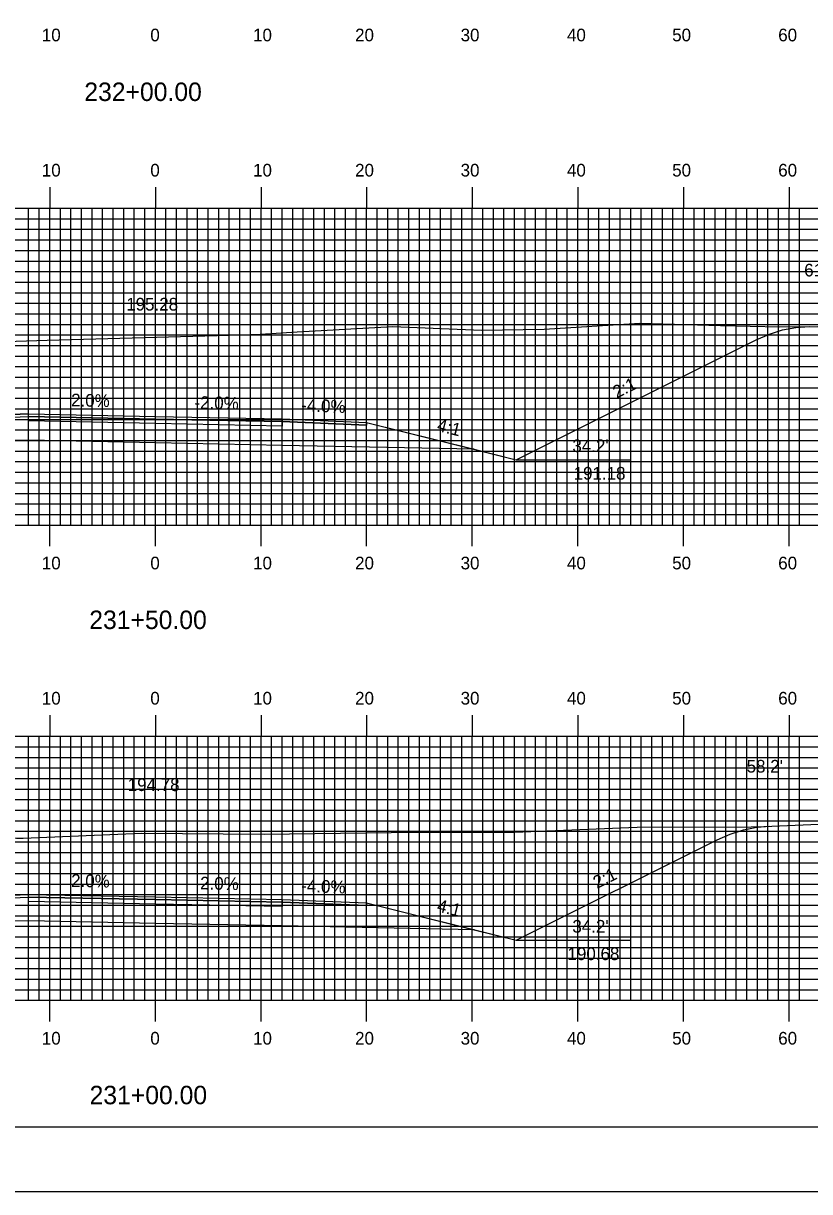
# Model space of a CAD drawing. Extents: x 1799568 to 1799912, y 442591 to 442811.
# Drawn here: x 1799721.5 to 1799796, y 442590.5 to 442701.2 of the extents above; entities that cross this region are included whole.
import ezdxf

# ---------------------------------------------------------------- set-up
doc = ezdxf.new("R2010")
doc.units = 0
for name, color, linetype in [('ANNOTATION', 7, 'Continuous'), ('BORDER', 7, 'Continuous'), ('D_Roadway_Centerline', 7, 'Continuous'), ('D_Roadway_Centerline_Text', 7, 'Continuous'), ('D_Roadway_Edge_Shoulder', 7, 'Continuous'), ('D_Roadway_Edge_TW', 7, 'Continuous'), ('D_Roadway_Pavement', 7, 'Continuous'), ('D_Roadway_SlopeLines', 7, 'Continuous'), ('D_Roadway_SubGrade', 7, 'Continuous'), ('D_Text_Standard', 7, 'Continuous'), ('H_V ANNOTATION', 7, 'Continuous'), ('MAJOR', 7, 'Continuous'), ('MINOR', 7, 'Continuous'), ('PDRAIN', 7, 'Continuous'), ('PLOT BOUNDARY', 7, 'Continuous'), ('S_Roadway_Centerline', 7, 'Continuous')]:
    doc.layers.add(name, color=color, linetype=linetype)

msp = doc.modelspace()

# ---------------------------------------------------------------- linework, layer by layer
at = {"layer": 'BORDER'}
msp.add_lwpolyline([(1799584.41, 442596.67), (1799904.41, 442596.67), (1799904.41, 442806.67), (1799584.41, 442806.67)], close=True, dxfattribs=at)
at = {"layer": 'D_Roadway_Centerline'}
for points in [[(1799677.91, 442669.95), (1799679.16, 442669.91), (1799680.41, 442669.7), (1799681.66, 442669.33), (1799682.91, 442668.79), (1799699.84, 442660.33), (1799703.84, 442661.33), (1799714.01, 442663.87), (1799722.01, 442664.19), (1799734.01, 442663.95), (1799746.01, 442663.71), (1799754.01, 442663.39), (1799764.18, 442660.85), (1799768.18, 442659.85), (1799790.9, 442671.2), (1799792.15, 442671.75), (1799793.4, 442672.14), (1799794.65, 442672.38), (1799795.9, 442672.47)], [(1799679.47, 442623.7), (1799680.72, 442623.65), (1799681.97, 442623.43), (1799683.22, 442623.05), (1799684.47, 442622.51), (1799699.84, 442614.83), (1799703.84, 442615.83), (1799714.01, 442618.37), (1799722.01, 442618.69), (1799734.01, 442618.45), (1799746.01, 442618.21), (1799754.01, 442617.89), (1799764.18, 442615.35), (1799768.18, 442614.35), (1799787.19, 442623.85), (1799788.44, 442624.4), (1799789.69, 442624.8), (1799790.94, 442625.05), (1799792.19, 442625.15)]]:
    msp.add_lwpolyline(points, dxfattribs=at)
at = {"layer": 'D_Roadway_Edge_Shoulder'}
for points in [[(1799722.01, 442664.19), (1799714.01, 442663.87), (1799714.01, 442663.62), (1799722.01, 442663.94)], [(1799746.01, 442663.71), (1799754.01, 442663.39), (1799754.01, 442663.14), (1799746.01, 442663.46)], [(1799722.01, 442618.69), (1799714.01, 442618.37), (1799714.01, 442618.12), (1799722.01, 442618.44)], [(1799746.01, 442618.21), (1799754.01, 442617.89), (1799754.01, 442617.64), (1799746.01, 442617.96)]]:
    msp.add_lwpolyline(points, close=True, dxfattribs=at)
at = {"layer": 'D_Roadway_Edge_TW'}
for points in [[(1799722.01, 442663.94), (1799722.01, 442664.19), (1799734.01, 442663.95), (1799746.01, 442663.71), (1799746.01, 442663.46), (1799734.01, 442663.7)], [(1799722.01, 442618.44), (1799722.01, 442618.69), (1799734.01, 442618.45), (1799746.01, 442618.21), (1799746.01, 442617.96), (1799734.01, 442618.2)]]:
    msp.add_lwpolyline(points, close=True, dxfattribs=at)
at = {"layer": 'D_Roadway_Pavement'}
for points in [[(1799722.01, 442663.52), (1799722.01, 442663.94), (1799734.01, 442663.7), (1799746.01, 442663.46), (1799746.01, 442663.04), (1799734.01, 442663.28)], [(1799722.01, 442618.02), (1799722.01, 442618.44), (1799734.01, 442618.2), (1799746.01, 442617.96), (1799746.01, 442617.54), (1799734.01, 442617.78)]]:
    msp.add_lwpolyline(points, close=True, dxfattribs=at)
at = {"layer": 'D_Roadway_SlopeLines'}
for points in [[(1799768.18, 442659.85), (1799790.9, 442671.2), (1799792.15, 442671.75), (1799793.4, 442672.14), (1799794.65, 442672.38), (1799795.9, 442672.47)], [(1799754.01, 442663.39), (1799768.18, 442659.85)], [(1799768.18, 442614.35), (1799787.19, 442623.85), (1799788.44, 442624.4), (1799789.69, 442624.8), (1799790.94, 442625.05), (1799792.19, 442625.15)], [(1799754.01, 442617.89), (1799768.18, 442614.35)]]:
    msp.add_lwpolyline(points, dxfattribs=at)
at = {"layer": 'D_Roadway_SubGrade'}
for points in [[(1799722.01, 442661.69), (1799703.84, 442661.33), (1799714.01, 442663.87), (1799714.01, 442663.62), (1799722.01, 442663.94), (1799734.01, 442663.7), (1799746.01, 442663.46), (1799754.01, 442663.14), (1799754.01, 442663.39), (1799764.18, 442660.85), (1799746.01, 442661.21), (1799734.01, 442661.45)], [(1799722.01, 442616.19), (1799703.84, 442615.83), (1799714.01, 442618.37), (1799714.01, 442618.12), (1799722.01, 442618.44), (1799734.01, 442618.2), (1799746.01, 442617.96), (1799754.01, 442617.64), (1799754.01, 442617.89), (1799764.18, 442615.35), (1799746.01, 442615.71), (1799734.01, 442615.95)]]:
    msp.add_lwpolyline(points, close=True, dxfattribs=at)
at = {"layer": 'MAJOR'}
for p, q in [((1799724.01, 442685.67), (1799724.01, 442683.67)), ((1799734.01, 442685.67), (1799734.01, 442683.67)), ((1799744.01, 442685.67), (1799744.01, 442683.67)), ((1799754.01, 442685.67), (1799754.01, 442683.67)), ((1799764.01, 442685.67), (1799764.01, 442683.67)), ((1799774.01, 442685.67), (1799774.01, 442683.67)), ((1799784.01, 442685.67), (1799784.01, 442683.67)), ((1799794.01, 442685.67), (1799794.01, 442683.67)), ((1799594.01, 442683.67), (1799874.01, 442683.67)), ((1799594.01, 442683.67), (1799874.01, 442683.67)), ((1799724.01, 442653.67), (1799724.01, 442683.67)), ((1799734.01, 442653.67), (1799734.01, 442683.67)), ((1799744.01, 442653.67), (1799744.01, 442683.67)), ((1799754.01, 442653.67), (1799754.01, 442683.67)), ((1799764.01, 442653.67), (1799764.01, 442683.67)), ((1799774.01, 442653.67), (1799774.01, 442683.67)), ((1799784.01, 442653.67), (1799784.01, 442683.67)), ((1799794.01, 442653.67), (1799794.01, 442683.67)), ((1799594.01, 442678.67), (1799874.01, 442678.67)), ((1799594.01, 442673.67), (1799874.01, 442673.67)), ((1799594.01, 442668.67), (1799874.01, 442668.67)), ((1799594.01, 442663.67), (1799874.01, 442663.67)), ((1799594.01, 442658.67), (1799874.01, 442658.67)), ((1799594.01, 442653.67), (1799874.01, 442653.67)), ((1799594.01, 442653.67), (1799874.01, 442653.67)), ((1799724.01, 442651.66), (1799724.01, 442653.67)), ((1799734.01, 442651.66), (1799734.01, 442653.67)), ((1799744.01, 442651.66), (1799744.01, 442653.67)), ((1799754.01, 442651.66), (1799754.01, 442653.67)), ((1799764.01, 442651.66), (1799764.01, 442653.67)), ((1799774.01, 442651.66), (1799774.01, 442653.67)), ((1799784.01, 442651.66), (1799784.01, 442653.67)), ((1799794.01, 442651.66), (1799794.01, 442653.67)), ((1799724.01, 442635.67), (1799724.01, 442633.67)), ((1799734.01, 442635.67), (1799734.01, 442633.67)), ((1799744.01, 442635.67), (1799744.01, 442633.67)), ((1799754.01, 442635.67), (1799754.01, 442633.67)), ((1799764.01, 442635.67), (1799764.01, 442633.67)), ((1799774.01, 442635.67), (1799774.01, 442633.67)), ((1799784.01, 442635.67), (1799784.01, 442633.67)), ((1799794.01, 442635.67), (1799794.01, 442633.67)), ((1799594.01, 442633.67), (1799874.01, 442633.67)), ((1799594.01, 442633.67), (1799874.01, 442633.67)), ((1799724.01, 442608.67), (1799724.01, 442633.67)), ((1799734.01, 442608.67), (1799734.01, 442633.67)), ((1799744.01, 442608.67), (1799744.01, 442633.67)), ((1799754.01, 442608.67), (1799754.01, 442633.67)), ((1799764.01, 442608.67), (1799764.01, 442633.67)), ((1799774.01, 442608.67), (1799774.01, 442633.67)), ((1799784.01, 442608.67), (1799784.01, 442633.67)), ((1799794.01, 442608.67), (1799794.01, 442633.67)), ((1799594.01, 442628.67), (1799874.01, 442628.67)), ((1799594.01, 442623.67), (1799874.01, 442623.67)), ((1799594.01, 442618.67), (1799874.01, 442618.67)), ((1799594.01, 442613.67), (1799874.01, 442613.67)), ((1799594.01, 442608.67), (1799874.01, 442608.67)), ((1799594.01, 442608.67), (1799874.01, 442608.67)), ((1799724.01, 442606.66), (1799724.01, 442608.67)), ((1799734.01, 442606.66), (1799734.01, 442608.67)), ((1799744.01, 442606.66), (1799744.01, 442608.67)), ((1799754.01, 442606.66), (1799754.01, 442608.67)), ((1799764.01, 442606.66), (1799764.01, 442608.67)), ((1799774.01, 442606.66), (1799774.01, 442608.67)), ((1799784.01, 442606.66), (1799784.01, 442608.67)), ((1799794.01, 442606.66), (1799794.01, 442608.67))]:
    msp.add_line(p, q, dxfattribs=at)
at = {"layer": 'MINOR'}
for p, q in [((1799722.01, 442653.67), (1799722.01, 442683.67)), ((1799723.01, 442653.67), (1799723.01, 442683.67)), ((1799725.01, 442653.67), (1799725.01, 442683.67)), ((1799726.01, 442653.67), (1799726.01, 442683.67)), ((1799727.01, 442653.67), (1799727.01, 442683.67)), ((1799728.01, 442653.67), (1799728.01, 442683.67)), ((1799729.01, 442653.67), (1799729.01, 442683.67)), ((1799730.01, 442653.67), (1799730.01, 442683.67)), ((1799731.01, 442653.67), (1799731.01, 442683.67)), ((1799732.01, 442653.67), (1799732.01, 442683.67)), ((1799733.01, 442653.67), (1799733.01, 442683.67)), ((1799735.01, 442653.67), (1799735.01, 442683.67)), ((1799736.01, 442653.67), (1799736.01, 442683.67)), ((1799737.01, 442653.67), (1799737.01, 442683.67)), ((1799738.01, 442653.67), (1799738.01, 442683.67)), ((1799739.01, 442653.67), (1799739.01, 442683.67)), ((1799740.01, 442653.67), (1799740.01, 442683.67)), ((1799741.01, 442653.67), (1799741.01, 442683.67)), ((1799742.01, 442653.67), (1799742.01, 442683.67)), ((1799743.01, 442653.67), (1799743.01, 442683.67)), ((1799745.01, 442653.67), (1799745.01, 442683.67)), ((1799746.01, 442653.67), (1799746.01, 442683.67)), ((1799747.01, 442653.67), (1799747.01, 442683.67)), ((1799748.01, 442653.67), (1799748.01, 442683.67)), ((1799749.01, 442653.67), (1799749.01, 442683.67)), ((1799750.01, 442653.67), (1799750.01, 442683.67)), ((1799751.01, 442653.67), (1799751.01, 442683.67)), ((1799752.01, 442653.67), (1799752.01, 442683.67)), ((1799753.01, 442653.67), (1799753.01, 442683.67)), ((1799755.01, 442653.67), (1799755.01, 442683.67)), ((1799756.01, 442653.67), (1799756.01, 442683.67)), ((1799757.01, 442653.67), (1799757.01, 442683.67)), ((1799758.01, 442653.67), (1799758.01, 442683.67)), ((1799759.01, 442653.67), (1799759.01, 442683.67)), ((1799760.01, 442653.67), (1799760.01, 442683.67)), ((1799761.01, 442653.67), (1799761.01, 442683.67)), ((1799762.01, 442653.67), (1799762.01, 442683.67)), ((1799763.01, 442653.67), (1799763.01, 442683.67)), ((1799765.01, 442653.67), (1799765.01, 442683.67)), ((1799766.01, 442653.67), (1799766.01, 442683.67)), ((1799767.01, 442653.67), (1799767.01, 442683.67)), ((1799768.01, 442653.67), (1799768.01, 442683.67)), ((1799769.01, 442653.67), (1799769.01, 442683.67)), ((1799770.01, 442653.67), (1799770.01, 442683.67)), ((1799771.01, 442653.67), (1799771.01, 442683.67)), ((1799772.01, 442653.67), (1799772.01, 442683.67)), ((1799773.01, 442653.67), (1799773.01, 442683.67)), ((1799775.01, 442653.67), (1799775.01, 442683.67)), ((1799776.01, 442653.67), (1799776.01, 442683.67)), ((1799777.01, 442653.67), (1799777.01, 442683.67)), ((1799778.01, 442653.67), (1799778.01, 442683.67)), ((1799779.01, 442653.67), (1799779.01, 442683.67)), ((1799780.01, 442653.67), (1799780.01, 442683.67)), ((1799781.01, 442653.67), (1799781.01, 442683.67)), ((1799782.01, 442653.67), (1799782.01, 442683.67)), ((1799783.01, 442653.67), (1799783.01, 442683.67)), ((1799785.01, 442653.67), (1799785.01, 442683.67)), ((1799786.01, 442653.67), (1799786.01, 442683.67)), ((1799787.01, 442653.67), (1799787.01, 442683.67)), ((1799788.01, 442653.67), (1799788.01, 442683.67)), ((1799789.01, 442653.67), (1799789.01, 442683.67)), ((1799790.01, 442653.67), (1799790.01, 442683.67)), ((1799791.01, 442653.67), (1799791.01, 442683.67)), ((1799792.01, 442653.67), (1799792.01, 442683.67)), ((1799793.01, 442653.67), (1799793.01, 442683.67)), ((1799795.01, 442653.67), (1799795.01, 442683.67)), ((1799594.01, 442682.67), (1799874.01, 442682.67)), ((1799594.01, 442681.67), (1799874.01, 442681.67)), ((1799594.01, 442680.67), (1799874.01, 442680.67)), ((1799594.01, 442679.67), (1799874.01, 442679.67)), ((1799594.01, 442677.67), (1799874.01, 442677.67)), ((1799594.01, 442676.67), (1799874.01, 442676.67)), ((1799594.01, 442675.67), (1799874.01, 442675.67)), ((1799594.01, 442674.67), (1799874.01, 442674.67)), ((1799594.01, 442672.67), (1799874.01, 442672.67)), ((1799594.01, 442671.67), (1799874.01, 442671.67)), ((1799594.01, 442670.67), (1799874.01, 442670.67)), ((1799594.01, 442669.67), (1799874.01, 442669.67)), ((1799594.01, 442667.67), (1799874.01, 442667.67)), ((1799594.01, 442666.67), (1799874.01, 442666.67)), ((1799594.01, 442665.67), (1799874.01, 442665.67)), ((1799594.01, 442664.67), (1799874.01, 442664.67)), ((1799594.01, 442662.67), (1799874.01, 442662.67)), ((1799594.01, 442661.67), (1799874.01, 442661.67)), ((1799594.01, 442660.67), (1799874.01, 442660.67)), ((1799594.01, 442659.67), (1799874.01, 442659.67)), ((1799594.01, 442657.67), (1799874.01, 442657.67)), ((1799594.01, 442656.67), (1799874.01, 442656.67)), ((1799594.01, 442655.67), (1799874.01, 442655.67)), ((1799594.01, 442654.67), (1799874.01, 442654.67)), ((1799722.01, 442608.67), (1799722.01, 442633.67)), ((1799723.01, 442608.67), (1799723.01, 442633.67)), ((1799725.01, 442608.67), (1799725.01, 442633.67)), ((1799726.01, 442608.67), (1799726.01, 442633.67)), ((1799727.01, 442608.67), (1799727.01, 442633.67)), ((1799728.01, 442608.67), (1799728.01, 442633.67)), ((1799729.01, 442608.67), (1799729.01, 442633.67)), ((1799730.01, 442608.67), (1799730.01, 442633.67)), ((1799731.01, 442608.67), (1799731.01, 442633.67)), ((1799732.01, 442608.67), (1799732.01, 442633.67)), ((1799733.01, 442608.67), (1799733.01, 442633.67)), ((1799735.01, 442608.67), (1799735.01, 442633.67)), ((1799736.01, 442608.67), (1799736.01, 442633.67)), ((1799737.01, 442608.67), (1799737.01, 442633.67)), ((1799738.01, 442608.67), (1799738.01, 442633.67)), ((1799739.01, 442608.67), (1799739.01, 442633.67)), ((1799740.01, 442608.67), (1799740.01, 442633.67)), ((1799741.01, 442608.67), (1799741.01, 442633.67)), ((1799742.01, 442608.67), (1799742.01, 442633.67)), ((1799743.01, 442608.67), (1799743.01, 442633.67)), ((1799745.01, 442608.67), (1799745.01, 442633.67)), ((1799746.01, 442608.67), (1799746.01, 442633.67)), ((1799747.01, 442608.67), (1799747.01, 442633.67)), ((1799748.01, 442608.67), (1799748.01, 442633.67)), ((1799749.01, 442608.67), (1799749.01, 442633.67)), ((1799750.01, 442608.67), (1799750.01, 442633.67)), ((1799751.01, 442608.67), (1799751.01, 442633.67)), ((1799752.01, 442608.67), (1799752.01, 442633.67)), ((1799753.01, 442608.67), (1799753.01, 442633.67)), ((1799755.01, 442608.67), (1799755.01, 442633.67)), ((1799756.01, 442608.67), (1799756.01, 442633.67)), ((1799757.01, 442608.67), (1799757.01, 442633.67)), ((1799758.01, 442608.67), (1799758.01, 442633.67)), ((1799759.01, 442608.67), (1799759.01, 442633.67)), ((1799760.01, 442608.67), (1799760.01, 442633.67)), ((1799761.01, 442608.67), (1799761.01, 442633.67)), ((1799762.01, 442608.67), (1799762.01, 442633.67)), ((1799763.01, 442608.67), (1799763.01, 442633.67)), ((1799765.01, 442608.67), (1799765.01, 442633.67)), ((1799766.01, 442608.67), (1799766.01, 442633.67)), ((1799767.01, 442608.67), (1799767.01, 442633.67)), ((1799768.01, 442608.67), (1799768.01, 442633.67)), ((1799769.01, 442608.67), (1799769.01, 442633.67)), ((1799770.01, 442608.67), (1799770.01, 442633.67)), ((1799771.01, 442608.67), (1799771.01, 442633.67)), ((1799772.01, 442608.67), (1799772.01, 442633.67)), ((1799773.01, 442608.67), (1799773.01, 442633.67)), ((1799775.01, 442608.67), (1799775.01, 442633.67)), ((1799776.01, 442608.67), (1799776.01, 442633.67)), ((1799777.01, 442608.67), (1799777.01, 442633.67)), ((1799778.01, 442608.67), (1799778.01, 442633.67)), ((1799779.01, 442608.67), (1799779.01, 442633.67)), ((1799780.01, 442608.67), (1799780.01, 442633.67)), ((1799781.01, 442608.67), (1799781.01, 442633.67)), ((1799782.01, 442608.67), (1799782.01, 442633.67)), ((1799783.01, 442608.67), (1799783.01, 442633.67)), ((1799785.01, 442608.67), (1799785.01, 442633.67)), ((1799786.01, 442608.67), (1799786.01, 442633.67)), ((1799787.01, 442608.67), (1799787.01, 442633.67)), ((1799788.01, 442608.67), (1799788.01, 442633.67)), ((1799789.01, 442608.67), (1799789.01, 442633.67)), ((1799790.01, 442608.67), (1799790.01, 442633.67)), ((1799791.01, 442608.67), (1799791.01, 442633.67)), ((1799792.01, 442608.67), (1799792.01, 442633.67)), ((1799793.01, 442608.67), (1799793.01, 442633.67)), ((1799795.01, 442608.67), (1799795.01, 442633.67)), ((1799594.01, 442632.67), (1799874.01, 442632.67)), ((1799594.01, 442631.67), (1799874.01, 442631.67)), ((1799594.01, 442630.67), (1799874.01, 442630.67)), ((1799594.01, 442629.67), (1799874.01, 442629.67)), ((1799594.01, 442627.67), (1799874.01, 442627.67)), ((1799594.01, 442626.67), (1799874.01, 442626.67)), ((1799594.01, 442625.67), (1799874.01, 442625.67)), ((1799594.01, 442624.67), (1799874.01, 442624.67)), ((1799594.01, 442622.67), (1799874.01, 442622.67)), ((1799594.01, 442621.67), (1799874.01, 442621.67)), ((1799594.01, 442620.67), (1799874.01, 442620.67)), ((1799594.01, 442619.67), (1799874.01, 442619.67)), ((1799594.01, 442617.67), (1799874.01, 442617.67)), ((1799594.01, 442616.67), (1799874.01, 442616.67)), ((1799594.01, 442615.67), (1799874.01, 442615.67)), ((1799594.01, 442614.67), (1799874.01, 442614.67)), ((1799594.01, 442612.67), (1799874.01, 442612.67)), ((1799594.01, 442611.67), (1799874.01, 442611.67)), ((1799594.01, 442610.67), (1799874.01, 442610.67)), ((1799594.01, 442609.67), (1799874.01, 442609.67))]:
    msp.add_line(p, q, dxfattribs=at)
at = {"layer": 'PDRAIN'}
for p, q in [((1799768.18, 442659.85), (1799778.95, 442659.85)), ((1799768.18, 442614.35), (1799778.95, 442614.35))]:
    msp.add_line(p, q, dxfattribs=at)
at = {"layer": 'PLOT BOUNDARY'}
msp.add_lwpolyline([(1799568.22, 442590.55), (1799908.22, 442590.55), (1799908.22, 442810.55), (1799568.22, 442810.55)], close=True, dxfattribs=at)
at = {"layer": 'S_Roadway_Centerline'}
for points in [[(1799663.02, 442669.64), (1799669.83, 442669.67), (1799678.53, 442669.97), (1799685.88, 442670.24), (1799701.25, 442670.72), (1799709.09, 442670.84), (1799717.53, 442671.01), (1799720.83, 442671.08), (1799723.76, 442671.18), (1799741.01, 442671.65), (1799743.94, 442671.73), (1799747.42, 442671.95), (1799756.48, 442672.48), (1799764.88, 442672.12), (1799770.81, 442672.2), (1799779.87, 442672.79), (1799787.51, 442672.56), (1799793.12, 442672.45), (1799811.05, 442672.58)], [(1799663.42, 442623), (1799674.03, 442623.55), (1799676.18, 442623.63), (1799698.23, 442624.14), (1799698.46, 442624.15), (1799698.68, 442624.15), (1799707.54, 442624.1), (1799720.87, 442624.03), (1799721.49, 442624.03), (1799732.71, 442624.5), (1799744.31, 442624.41), (1799756.34, 442624.55), (1799768.01, 442624.58), (1799779.63, 442625.06), (1799790.42, 442625.1), (1799791.61, 442625.13), (1799813.9, 442626.06)]]:
    msp.add_lwpolyline(points, dxfattribs=at)

# ---------------------------------------------------------------- texts
at = {"layer": 'ANNOTATION'}
for s, rotation, p in [('2:1', 26.5651, (1799777.69, 442665.63)), ('2.0%', 358.8542, (1799726.02, 442664.91)), ('-2.0%', 358.8542, (1799737.7, 442664.68)), ('-4.0%', 357.7094, (1799747.8, 442664.44)), ('4:1', 345.9638, (1799760.6, 442662.6)), ('2.0%', 358.8542, (1799726.02, 442619.41)), ('2:1', 26.5651, (1799775.83, 442619.21)), ('-2.0%', 358.8542, (1799737.7, 442619.18)), ('-4.0%', 357.7094, (1799747.8, 442618.94)), ('4:1', 345.9638, (1799760.6, 442617.1))]:
    msp.add_text(s, height=1.2, rotation=rotation, dxfattribs=at).set_placement(p)
for s, p in [("34.2'", (1799773.49, 442660.57)), ('191.18', (1799773.61, 442657.97)), ("34.2'", (1799773.49, 442615.07)), ('190.68', (1799773.03, 442612.47))]:
    msp.add_text(s, height=1.2, dxfattribs=at).set_placement(p)
at = {"layer": 'D_Roadway_Centerline'}
for s, p in [('C', (1799734, 442663.95)), ('L', (1799734.01, 442663.94)), ('C', (1799734, 442618.45)), ('L', (1799734.01, 442618.44))]:
    msp.add_text(s, height=0.0146, dxfattribs=at).set_placement(p)
at = {"layer": 'D_Roadway_Centerline_Text'}
for s, p in [('195.28', (1799731.25, 442673.98)), ('194.78', (1799731.39, 442628.48))]:
    msp.add_text(s, height=1.2, dxfattribs=at).set_placement(p)
at = {"layer": 'D_Text_Standard'}
for s, p in [("61.9'", (1799795.44, 442677.21)), ("58.2'", (1799789.99, 442630.23))]:
    msp.add_text(s, height=1.2, dxfattribs=at).set_placement(p)
at = {"layer": 'H_V ANNOTATION'}
for s, height, p in [('10', 1.2, (1799723.26, 442699.47)), ('0', 1.2, (1799733.53, 442699.47)), ('10', 1.2, (1799743.26, 442699.47)), ('20', 1.2, (1799752.92, 442699.47)), ('30', 1.2, (1799762.91, 442699.47)), ('40', 1.2, (1799772.98, 442699.47)), ('50', 1.2, (1799782.94, 442699.47)), ('60', 1.2, (1799792.98, 442699.47)), ('232+00.00', 1.75, (1799727.28, 442693.82)), ('10', 1.2, (1799723.26, 442686.67)), ('0', 1.2, (1799733.53, 442686.67)), ('10', 1.2, (1799743.26, 442686.67)), ('20', 1.2, (1799752.92, 442686.67)), ('30', 1.2, (1799762.91, 442686.67)), ('40', 1.2, (1799772.98, 442686.67)), ('50', 1.2, (1799782.94, 442686.67)), ('60', 1.2, (1799792.98, 442686.67)), ('10', 1.2, (1799723.26, 442649.47)), ('0', 1.2, (1799733.53, 442649.47)), ('10', 1.2, (1799743.26, 442649.47)), ('20', 1.2, (1799752.92, 442649.47)), ('30', 1.2, (1799762.91, 442649.47)), ('40', 1.2, (1799772.98, 442649.47)), ('50', 1.2, (1799782.94, 442649.47)), ('60', 1.2, (1799792.98, 442649.47)), ('231+50.00', 1.75, (1799727.75, 442643.82)), ('10', 1.2, (1799723.26, 442636.67)), ('0', 1.2, (1799733.53, 442636.67)), ('10', 1.2, (1799743.26, 442636.67)), ('20', 1.2, (1799752.92, 442636.67)), ('30', 1.2, (1799762.91, 442636.67)), ('40', 1.2, (1799772.98, 442636.67)), ('50', 1.2, (1799782.94, 442636.67)), ('60', 1.2, (1799792.98, 442636.67)), ('10', 1.2, (1799723.26, 442604.47)), ('0', 1.2, (1799733.53, 442604.47)), ('10', 1.2, (1799743.26, 442604.47)), ('20', 1.2, (1799752.92, 442604.47)), ('30', 1.2, (1799762.91, 442604.47)), ('40', 1.2, (1799772.98, 442604.47)), ('50', 1.2, (1799782.94, 442604.47)), ('60', 1.2, (1799792.98, 442604.47)), ('231+00.00', 1.75, (1799727.78, 442598.82))]:
    msp.add_text(s, height=height, dxfattribs=at).set_placement(p)

doc.saveas('drawing.dxf')
